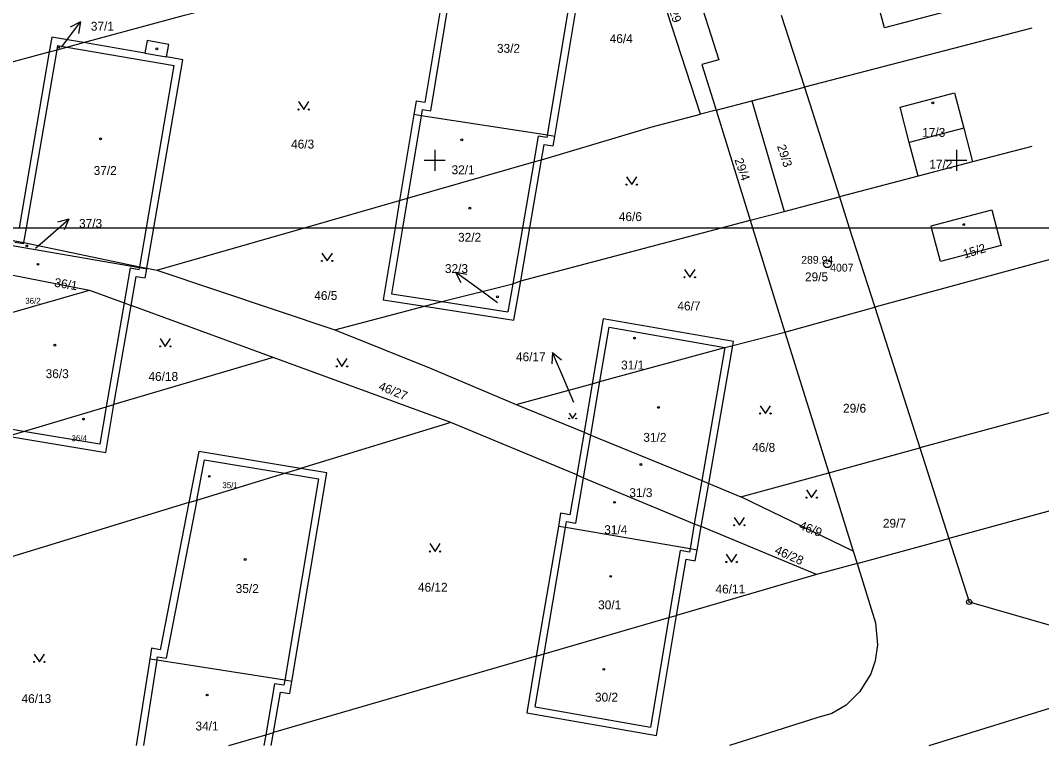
# Model space of a CAD drawing. Extents: x -599866 to -590076, y -1178039 to -1154526.
# Drawn here: x -599789.7 to -599691.8, y -1154756.1 to -1154686.6 of the extents above; entities that cross this region are included whole.
import ezdxf

# ---------------------------------------------------------------- set-up
doc = ezdxf.new("R2010")
doc.units = 0
for name, color, linetype in [('KN', 7, 'Continuous'), ('Rám', 7, 'Continuous'), ('Vrstva 5', 7, 'Continuous'), ('Vrstva 54', 7, 'Continuous'), ('Vrstva 55', 7, 'Continuous'), ('Vrstva 56', 7, 'Continuous')]:
    doc.layers.add(name, color=color, linetype=linetype)

msp = doc.modelspace()

# ---------------------------------------------------------------- linework, layer by layer
at = {"layer": 'KN'}
for p, q in [((-599724.53, -1154695.57), (-599731.32, -1154674.72)), ((-599739.18, -1154697.59), (-599735.95, -1154678.13)), ((-599750.37, -1154695.25), (-599747.72, -1154679.26)), ((-599716.78, -1154686.08), (-599714.57, -1154692.99)), ((-599785.75, -1154689.12), (-599783.944, -1154686.723)), ((-599783.944, -1154686.723), (-599784.947, -1154687.222)), ((-599783.944, -1154686.723), (-599784.147, -1154687.824)), ((-599692.76, -1154687.329), (-599714.57, -1154692.99)), ((-599789.134, -1154706.45), (-599786.2, -1154689.4)), ((-599786.2, -1154689.4), (-599786.13, -1154689)), ((-599786.13, -1154689), (-599785.27, -1154689.15)), ((-599785.78, -1154689.16), (-599785.75, -1154689.12)), ((-599785.27, -1154689.15), (-599774.96, -1154690.92)), ((-599777.78, -1154689.72), (-599783.66, -1154688.71)), ((-599806.74, -1154694.958), (-599786.94, -1154689.6)), ((-599777.78, -1154689.72), (-599775.71, -1154690.08)), ((-599777.629, -1154706.45), (-599774.96, -1154690.92)), ((-599719.61, -1154694.29), (-599714.57, -1154692.99)), ((-599714.57, -1154692.99), (-599711.21, -1154703.49)), ((-599723.03, -1154695.18), (-599719.61, -1154694.29)), ((-599719.61, -1154694.29), (-599716.52, -1154704.88)), ((-599751.21, -1154695.11), (-599751.31, -1154695.72)), ((-599751.21, -1154695.11), (-599750.37, -1154695.25)), ((-599723.03, -1154695.18), (-599724.53, -1154695.57)), ((-599723.03, -1154695.18), (-599719.75, -1154705.72)), ((-599752.01, -1154695.61), (-599753.37, -1154703.84)), ((-599751.31, -1154695.72), (-599752.62, -1154703.63)), ((-599729.27, -1154696.8), (-599724.53, -1154695.57)), ((-599739.75, -1154699.94), (-599729.27, -1154696.8)), ((-599699.29, -1154696.91), (-599704.51, -1154698.28)), ((-599699.29, -1154696.91), (-599698.44, -1154700.15)), ((-599740.07, -1154697.67), (-599740.5, -1154700.15)), ((-599739.22, -1154697.81), (-599740.07, -1154697.67)), ((-599739.22, -1154697.81), (-599739.18, -1154697.59)), ((-599703.66, -1154701.52), (-599704.51, -1154698.28)), ((-599692.76, -1154698.668), (-599698.44, -1154700.15)), ((-599740.5, -1154700.15), (-599741.589, -1154706.45)), ((-599740.873, -1154706.45), (-599739.75, -1154699.94)), ((-599698.44, -1154700.15), (-599703.66, -1154701.52)), ((-599703.66, -1154701.52), (-599711.21, -1154703.49)), ((-599762.466, -1154706.45), (-599753.37, -1154703.84)), ((-599752.62, -1154703.63), (-599753.088, -1154706.45)), ((-599716.52, -1154704.88), (-599711.21, -1154703.49)), ((-599711.21, -1154703.49), (-599710.261, -1154706.45)), ((-599719.75, -1154705.72), (-599716.52, -1154704.88)), ((-599787.34, -1154707.6), (-599785.075, -1154705.631)), ((-599785.075, -1154705.631), (-599786.159, -1154705.91)), ((-599785.075, -1154705.631), (-599785.502, -1154706.666)), ((-599722.514, -1154706.45), (-599719.75, -1154705.72)), ((-599719.75, -1154705.72), (-599719.524, -1154706.45)), ((-599789.38, -1154707.88), (-599789.134, -1154706.45)), ((-599778.27, -1154710.18), (-599777.629, -1154706.45)), ((-599776.65, -1154710.52), (-599762.466, -1154706.45)), ((-599753.088, -1154706.45), (-599754.14, -1154712.78)), ((-599741.589, -1154706.45), (-599742.52, -1154711.84)), ((-599741.75, -1154711.53), (-599722.514, -1154706.45)), ((-599741.75, -1154711.53), (-599740.873, -1154706.45)), ((-599719.524, -1154706.45), (-599716.43, -1154716.46)), ((-599710.261, -1154706.45), (-599707.82, -1154714.06)), ((-599680.42, -1154706.63), (-599707.82, -1154714.06)), ((-599790.25, -1154707.82), (-599789.39, -1154707.96)), ((-599789.39, -1154707.96), (-599789.38, -1154707.88)), ((-599788.25, -1154708.4), (-599787.34, -1154707.6)), ((-599779.18, -1154710.3), (-599779.76, -1154713.66)), ((-599779.18, -1154710.3), (-599778.32, -1154710.45)), ((-599778.32, -1154710.45), (-599778.29, -1154710.3)), ((-599778.29, -1154710.3), (-599778.27, -1154710.18)), ((-599777.6, -1154710.42), (-599777.59, -1154710.33)), ((-599777.59, -1154710.33), (-599776.65, -1154710.52)), ((-599776.65, -1154710.52), (-599759.58, -1154716.24)), ((-599745.59, -1154712.47), (-599748.018, -1154710.706)), ((-599748.018, -1154710.706), (-599746.913, -1154710.89)), ((-599748.018, -1154710.706), (-599747.502, -1154711.7)), ((-599742.52, -1154711.84), (-599742.98, -1154714.5)), ((-599783.09, -1154712.44), (-599779.76, -1154713.66)), ((-599754.14, -1154712.78), (-599749.31, -1154713.53)), ((-599743.98, -1154713.65), (-599745.59, -1154712.47)), ((-599779.76, -1154713.66), (-599781.48, -1154723.62)), ((-599780.74, -1154723.39), (-599779.1, -1154713.9)), ((-599779.76, -1154713.66), (-599779.1, -1154713.9)), ((-599765.48, -1154718.89), (-599779.1, -1154713.9)), ((-599759.58, -1154716.24), (-599750.99, -1154713.97)), ((-599749.31, -1154713.53), (-599742.98, -1154714.5)), ((-599716.43, -1154716.46), (-599707.82, -1154714.06)), ((-599707.82, -1154714.06), (-599703.5, -1154727.55)), ((-599734.16, -1154721.19), (-599733.27, -1154715.99)), ((-599733.27, -1154715.99), (-599722.18, -1154717.92)), ((-599721.43, -1154717.72), (-599716.43, -1154716.46)), ((-599716.43, -1154716.46), (-599712.23, -1154729.93)), ((-599734.16, -1154721.19), (-599722.18, -1154717.92)), ((-599722.18, -1154717.92), (-599724.4, -1154730.68)), ((-599723.74, -1154730.96), (-599721.43, -1154717.72)), ((-599722.18, -1154717.92), (-599721.43, -1154717.72)), ((-599664.9, -1154717.05), (-599703.5, -1154727.55)), ((-599765.48, -1154718.89), (-599780.74, -1154723.39)), ((-599748.46, -1154725.12), (-599765.48, -1154718.89)), ((-599738.703, -1154718.388), (-599738.772, -1154719.505)), ((-599737.53, -1154721.15), (-599738.703, -1154718.388)), ((-599738.703, -1154718.388), (-599737.85, -1154719.114)), ((-599742.18, -1154723.38), (-599734.9, -1154721.39)), ((-599736.65, -1154723.2), (-599737.53, -1154721.15)), ((-599734.9, -1154721.39), (-599735.69, -1154726.05)), ((-599735.03, -1154726.32), (-599734.16, -1154721.19)), ((-599734.9, -1154721.39), (-599734.16, -1154721.19)), ((-599781.48, -1154723.62), (-599782.1, -1154727.19)), ((-599742.18, -1154723.38), (-599735.69, -1154726.05)), ((-599789.41, -1154725.96), (-599793.18, -1154725.32)), ((-599748.46, -1154725.12), (-599762.86, -1154729.52)), ((-599736.39, -1154730.13), (-599748.46, -1154725.12)), ((-599782.1, -1154727.19), (-599789.41, -1154725.96)), ((-599735.69, -1154726.05), (-599736.39, -1154730.13)), ((-599735.73, -1154730.41), (-599735.03, -1154726.32)), ((-599735.69, -1154726.05), (-599735.03, -1154726.32)), ((-599735.03, -1154726.32), (-599724.4, -1154730.68)), ((-599712.23, -1154729.93), (-599703.5, -1154727.55)), ((-599703.5, -1154727.55), (-599700.72, -1154736.23)), ((-599772.8, -1154732.55), (-599772.05, -1154728.68)), ((-599772.05, -1154728.68), (-599764.35, -1154729.97)), ((-599761.14, -1154730.51), (-599764.38, -1154749.81)), ((-599764.35, -1154729.97), (-599761.14, -1154730.51)), ((-599736.47, -1154734.76), (-599735.73, -1154730.41)), ((-599736.39, -1154730.13), (-599735.73, -1154730.41)), ((-599735.73, -1154730.41), (-599725.12, -1154734.82)), ((-599720.66, -1154732.22), (-599712.23, -1154729.93)), ((-599712.23, -1154729.93), (-599709.88, -1154737.45)), ((-599724.4, -1154730.68), (-599725.12, -1154734.82)), ((-599724.46, -1154735.09), (-599723.74, -1154730.96)), ((-599724.4, -1154730.68), (-599723.74, -1154730.96)), ((-599723.74, -1154730.96), (-599720.66, -1154732.22)), ((-599681.2, -1154730.88), (-599700.72, -1154736.23)), ((-599772.8, -1154732.55), (-599775.75, -1154747.68)), ((-599709.88, -1154737.45), (-599720.66, -1154732.22)), ((-599773.56, -1154732.78), (-599802.38, -1154741.58)), ((-599738.15, -1154735.06), (-599740.26, -1154747.5)), ((-599739.51, -1154747.28), (-599737.46, -1154735.18)), ((-599737.46, -1154735.18), (-599737.36, -1154734.61)), ((-599737.36, -1154734.61), (-599736.47, -1154734.76)), ((-599725.12, -1154734.82), (-599725.53, -1154737.23)), ((-599725.12, -1154734.82), (-599724.46, -1154735.09)), ((-599724.85, -1154737.35), (-599724.46, -1154735.09)), ((-599713.39, -1154739.69), (-599724.46, -1154735.09)), ((-599709.51, -1154738.63), (-599700.72, -1154736.23)), ((-599726.48, -1154737.39), (-599727.55, -1154743.81)), ((-599725.59, -1154737.55), (-599726.48, -1154737.39)), ((-599725.53, -1154737.23), (-599725.59, -1154737.55)), ((-599709.88, -1154737.45), (-599709.51, -1154738.63)), ((-599709.51, -1154738.63), (-599713.39, -1154739.69)), ((-599713.39, -1154739.69), (-599726.81, -1154743.59)), ((-599727.55, -1154743.81), (-599729.31, -1154754.29)), ((-599740.37, -1154752.35), (-599739.51, -1154747.28)), ((-599777.32, -1154747.78), (-599778.631, -1154756.065)), ((-599776.63, -1154747.89), (-599777.917, -1154756.065)), ((-599776.63, -1154747.89), (-599776.58, -1154747.55)), ((-599776.58, -1154747.55), (-599775.75, -1154747.68)), ((-599740.26, -1154747.5), (-599765.46, -1154754.82)), ((-599702.59, -1154756.065), (-599675.96, -1154747.79)), ((-599765.36, -1154750.15), (-599766.2, -1154755.04)), ((-599764.46, -1154750.29), (-599765.36, -1154750.15)), ((-599764.38, -1154749.81), (-599764.46, -1154750.29)), ((-599740.37, -1154752.35), (-599729.31, -1154754.29)), ((-599769.726, -1154756.065), (-599766.2, -1154755.04)), ((-599766.2, -1154755.04), (-599766.376, -1154756.065)), ((-599766.2, -1154755.04), (-599765.46, -1154754.82))]:
    msp.add_line(p, q, dxfattribs=at)
for points in [[(-599738.49, -1154697.7), (-599735.14, -1154677.55), (-599736.71, -1154677.29)], [(-599726.87, -1154677.54), (-599722.78, -1154690.35), (-599724.39, -1154690.82), (-599723.03, -1154695.18)], [(-599783.66, -1154688.71), (-599773.98, -1154686.09), (-599748.46, -1154679.46)], [(-599748.46, -1154679.46), (-599750.95, -1154694.45), (-599751.79, -1154694.31), (-599752.01, -1154695.61)], [(-599701.97, -1154682.19), (-599701.05, -1154685.76), (-599706.9, -1154687.29), (-599707.83, -1154683.73)], [(-599783.66, -1154688.71), (-599786.7, -1154688.19), (-599786.94, -1154689.6)], [(-599775.71, -1154690.08), (-599775.5, -1154688.88), (-599777.57, -1154688.52), (-599777.78, -1154689.72)], [(-599786.94, -1154689.6), (-599786.2, -1154689.4), (-599785.27, -1154689.15), (-599783.66, -1154688.71)], [(-599786.94, -1154689.6), (-599789.838, -1154706.45)], [(-599776.922, -1154706.45), (-599774.15, -1154690.35), (-599775.71, -1154690.08)], [(-599763.06, -1154694.37), (-599762.56, -1154695.12), (-599762.06, -1154694.37)], [(-599704.51, -1154698.28), (-599705.4, -1154694.89), (-599700.18, -1154693.52), (-599699.29, -1154696.91)], [(-599738.49, -1154697.7), (-599739.18, -1154697.59), (-599751.31, -1154695.72), (-599752.01, -1154695.61)], [(-599739.75, -1154699.94), (-599739.5, -1154698.47), (-599738.64, -1154698.61), (-599738.49, -1154697.7)], [(-599753.37, -1154703.84), (-599752.62, -1154703.63), (-599740.5, -1154700.15), (-599739.75, -1154699.94)], [(-599731.62, -1154701.569), (-599731.12, -1154702.32), (-599730.62, -1154701.569)], [(-599753.37, -1154703.84), (-599753.803, -1154706.45)], [(-599702.37, -1154706.45), (-599702.42, -1154706.26), (-599696.59, -1154704.74), (-599696.145, -1154706.45)], [(-599777.59, -1154710.33), (-599776.922, -1154706.45)], [(-599753.803, -1154706.45), (-599754.95, -1154713.36), (-599750.99, -1154713.97)], [(-599701.52, -1154709.7), (-599702.37, -1154706.45)], [(-599696.145, -1154706.45), (-599695.7, -1154708.16), (-599701.52, -1154709.7)], [(-599777.6, -1154710.42), (-599778.29, -1154710.3), (-599790.32, -1154708.23), (-599791, -1154708.11)], [(-599790.91, -1154707.57), (-599789.38, -1154707.88), (-599778.27, -1154710.18), (-599777.59, -1154710.33)], [(-599760.81, -1154708.88), (-599760.31, -1154709.63), (-599759.81, -1154708.88)], [(-599791.45, -1154710.79), (-599790.77, -1154710.92), (-599783.09, -1154712.44)], [(-599779.1, -1154713.9), (-599778.62, -1154711.11), (-599777.75, -1154711.26), (-599777.6, -1154710.42)], [(-599726.05, -1154710.44), (-599725.55, -1154711.19), (-599725.05, -1154710.44)], [(-599750.99, -1154713.97), (-599749.31, -1154713.53), (-599742.52, -1154711.84), (-599741.75, -1154711.53)], [(-599750.99, -1154713.97), (-599742.4, -1154715.29), (-599741.75, -1154711.53)], [(-599792.17, -1154715.04), (-599791.42, -1154714.83), (-599783.09, -1154712.44)], [(-599721.43, -1154717.72), (-599721.37, -1154717.35), (-599733.84, -1154715.18), (-599734.9, -1154721.39)], [(-599759.58, -1154716.24), (-599750.49, -1154719.88), (-599742.18, -1154723.38)], [(-599776.32, -1154717.069), (-599775.82, -1154717.82), (-599775.32, -1154717.069)], [(-599759.39, -1154718.98), (-599758.89, -1154719.73), (-599758.39, -1154718.98)], [(-599790.93, -1154726.41), (-599789.41, -1154725.96), (-599781.48, -1154723.62), (-599780.74, -1154723.39)], [(-599790.93, -1154726.41), (-599781.53, -1154728), (-599780.74, -1154723.39)], [(-599718.8, -1154723.499), (-599718.3, -1154724.25), (-599717.8, -1154723.499)], [(-599737.115, -1154724.227), (-599736.78, -1154724.73), (-599736.445, -1154724.227)], [(-599762.86, -1154729.52), (-599772.61, -1154727.88), (-599773.56, -1154732.78)], [(-599773.56, -1154732.78), (-599772.8, -1154732.55), (-599764.35, -1154729.97), (-599762.86, -1154729.52)], [(-599763.69, -1154749.92), (-599760.33, -1154729.94), (-599762.86, -1154729.52)], [(-599736.39, -1154730.13), (-599737.04, -1154733.95), (-599737.94, -1154733.8), (-599738.15, -1154735.06)], [(-599714.37, -1154731.559), (-599713.87, -1154732.31), (-599713.37, -1154731.559)], [(-599773.56, -1154732.78), (-599776.31, -1154746.88), (-599777.16, -1154746.74), (-599777.32, -1154747.78)], [(-599721.3, -1154734.2), (-599720.8, -1154734.95), (-599720.3, -1154734.2)], [(-599724.85, -1154737.35), (-599725.53, -1154737.23), (-599737.46, -1154735.18), (-599738.15, -1154735.06)], [(-599700.72, -1154736.23), (-599698.78, -1154742.3), (-599687.01, -1154745.68), (-599677.64, -1154742.48)], [(-599750.47, -1154736.72), (-599749.97, -1154737.47), (-599749.47, -1154736.72)], [(-599726.81, -1154743.59), (-599725.91, -1154738.21), (-599725.03, -1154738.37), (-599724.85, -1154737.35)], [(-599722.05, -1154737.73), (-599721.55, -1154738.48), (-599721.05, -1154737.73)], [(-599709.51, -1154738.63), (-599707.74, -1154744.3), (-599707.55, -1154746.42), (-599707.78, -1154747.96), (-599708.21, -1154749.19), (-599709.26, -1154750.87), (-599710.56, -1154752.2), (-599711.92, -1154752.98), (-599713.38, -1154753.41), (-599721.735, -1154756.065)], [(-599740.26, -1154747.5), (-599741.18, -1154752.92), (-599728.74, -1154755.11), (-599726.81, -1154743.59)], [(-599740.26, -1154747.5), (-599739.51, -1154747.28), (-599727.55, -1154743.81), (-599726.81, -1154743.59)], [(-599788.39, -1154747.299), (-599787.89, -1154748.05), (-599787.39, -1154747.299)], [(-599763.69, -1154749.92), (-599764.38, -1154749.81), (-599776.63, -1154747.89), (-599777.32, -1154747.78)], [(-599765.46, -1154754.82), (-599764.79, -1154750.95), (-599763.88, -1154751.09), (-599763.69, -1154749.92)], [(-599765.674, -1154756.065), (-599765.46, -1154754.82)]]:
    msp.add_lwpolyline(points, dxfattribs=at)
for centre, radius in [((-599786.002, -1154689.18), 0.0586), ((-599776.633, -1154689.31), 0.0875), ((-599702.253, -1154694.49), 0.0875), ((-599763.06, -1154695.12), 0.05), ((-599762.06, -1154695.12), 0.05), ((-599782.023, -1154697.93), 0.0875), ((-599747.393, -1154698.03), 0.0875), ((-599731.62, -1154702.32), 0.05), ((-599730.62, -1154702.32), 0.05), ((-599746.633, -1154704.57), 0.0875), ((-599699.293, -1154706.15), 0.0875), ((-599789.083, -1154708.19), 0.0875), ((-599788.023, -1154709.95), 0.0875), ((-599760.81, -1154709.63), 0.05), ((-599759.81, -1154709.63), 0.05), ((-599726.05, -1154711.19), 0.05), ((-599725.05, -1154711.19), 0.05), ((-599743.983, -1154713.07), 0.0875), ((-599730.843, -1154717.02), 0.0875), ((-599786.413, -1154717.7), 0.0875), ((-599776.32, -1154717.82), 0.05), ((-599775.32, -1154717.82), 0.05), ((-599759.39, -1154719.73), 0.05), ((-599758.39, -1154719.73), 0.05), ((-599728.553, -1154723.66), 0.0875), ((-599783.653, -1154724.78), 0.0875), ((-599737.115, -1154724.73), 0.0335), ((-599736.445, -1154724.73), 0.0335), ((-599718.8, -1154724.25), 0.05), ((-599717.8, -1154724.25), 0.05), ((-599730.233, -1154729.13), 0.0875), ((-599771.603, -1154730.27), 0.0875), ((-599714.37, -1154732.31), 0.05), ((-599713.37, -1154732.31), 0.05), ((-599732.753, -1154732.76), 0.0875), ((-599721.3, -1154734.95), 0.05), ((-599720.3, -1154734.95), 0.05), ((-599750.47, -1154737.47), 0.05), ((-599749.47, -1154737.47), 0.05), ((-599768.163, -1154738.24), 0.0875), ((-599722.05, -1154738.48), 0.05), ((-599721.05, -1154738.48), 0.05), ((-599733.133, -1154739.85), 0.0875), ((-599698.78, -1154742.3), 0.25), ((-599698.78, -1154742.3), 0.0152), ((-599788.39, -1154748.05), 0.05), ((-599787.39, -1154748.05), 0.05), ((-599733.803, -1154748.76), 0.0875), ((-599771.813, -1154751.22), 0.0875)]:
    msp.add_circle(centre, radius, dxfattribs=at)
at = {"layer": 'Rám'}
for points in [[(-599806.74, -1154706.45), (-599701.74, -1154706.45)], [(-599701.74, -1154706.45), (-599596.74, -1154706.45)]]:
    msp.add_lwpolyline(points, dxfattribs=at)
at = {"layer": 'Vrstva 5'}
for p, q in [((-599750, -1154699), (-599750, -1154701)), ((-599700, -1154699), (-599700, -1154701)), ((-599749, -1154700), (-599751, -1154700)), ((-599699, -1154700), (-599701, -1154700))]:
    msp.add_line(p, q, dxfattribs=at)
at = {"layer": 'Vrstva 56'}
for radius in [0.375, 0.375, 0.0179, 0.0179]:
    msp.add_circle((-599712.37, -1154709.9), radius, dxfattribs=at)

# ---------------------------------------------------------------- texts
at = {"layer": 'KN'}
for s, rotation, p in [('46/29', 288, (-599728.013, -1154684.173)), ('29/3', 288, (-599717.201, -1154698.632)), ('29/4', 289, (-599721.284, -1154699.939)), ('15/2', 17, (-599699.211, -1154709.41)), ('36/1', 351, (-599786.5, -1154712.092)), ('46/27', 338, (-599755.462, -1154721.948)), ('46/9', 339, (-599715.145, -1154735.302)), ('46/28', 336, (-599717.488, -1154737.635))]:
    msp.add_text(s, height=0.85, rotation=rotation, dxfattribs=at).set_placement(p)
for s, height, p in [('37/1', 0.85, (-599782.96, -1154687.57)), ('46/4', 0.85, (-599733.226, -1154688.756)), ('33/2', 0.85, (-599744.035, -1154689.69)), ('17/3', 0.85, (-599703.27, -1154697.74)), ('46/3', 0.85, (-599763.766, -1154698.86)), ('17/2', 0.85, (-599702.596, -1154700.79)), ('37/2', 0.85, (-599782.689, -1154701.39)), ('32/1', 0.85, (-599748.383, -1154701.32)), ('46/6', 0.85, (-599732.349, -1154705.81)), ('37/3', 0.85, (-599784.09, -1154706.46)), ('32/2', 0.85, (-599747.762, -1154707.79)), ('32/3', 0.85, (-599749.02, -1154710.79)), ('29/5', 0.85, (-599714.509, -1154711.58)), ('46/5', 0.85, (-599761.546, -1154713.37)), ('36/2', 0.57, (-599789.248, -1154713.74)), ('46/7', 0.85, (-599726.739, -1154714.37)), ('46/17', 0.85, (-599742.211, -1154719.24)), ('31/1', 0.85, (-599732.134, -1154720.03)), ('36/3', 0.85, (-599787.292, -1154720.86)), ('46/18', 0.85, (-599777.44, -1154721.13)), ('29/6', 0.85, (-599710.862, -1154724.17)), ('36/4', 0.57, (-599784.813, -1154726.9)), ('31/2', 0.85, (-599730.003, -1154726.96)), ('46/8', 0.85, (-599719.579, -1154727.92)), ('35/1', 0.57, (-599770.354, -1154731.4)), ('31/3', 0.85, (-599731.346, -1154732.26)), ('29/7', 0.85, (-599707.042, -1154735.19)), ('31/4', 0.85, (-599733.75, -1154735.81)), ('46/12', 0.85, (-599751.604, -1154741.32)), ('35/2', 0.85, (-599769.075, -1154741.45)), ('46/11', 0.85, (-599723.084, -1154741.49)), ('30/1', 0.85, (-599734.336, -1154743.01)), ('46/13', 0.85, (-599789.607, -1154751.99)), ('30/2', 0.85, (-599734.635, -1154751.85)), ('34/1', 0.85, (-599772.93, -1154754.62))]:
    msp.add_text(s, height=height, dxfattribs=at).set_placement(p)
at = {"layer": 'Vrstva 54'}
msp.add_text('289.94 ', height=0.75, dxfattribs=at).set_placement((-599714.87, -1154709.9))
at = {"layer": 'Vrstva 55'}
msp.add_text(' 4007', height=0.75, dxfattribs=at).set_placement((-599712.37, -1154710.65))

doc.saveas('drawing.dxf')
